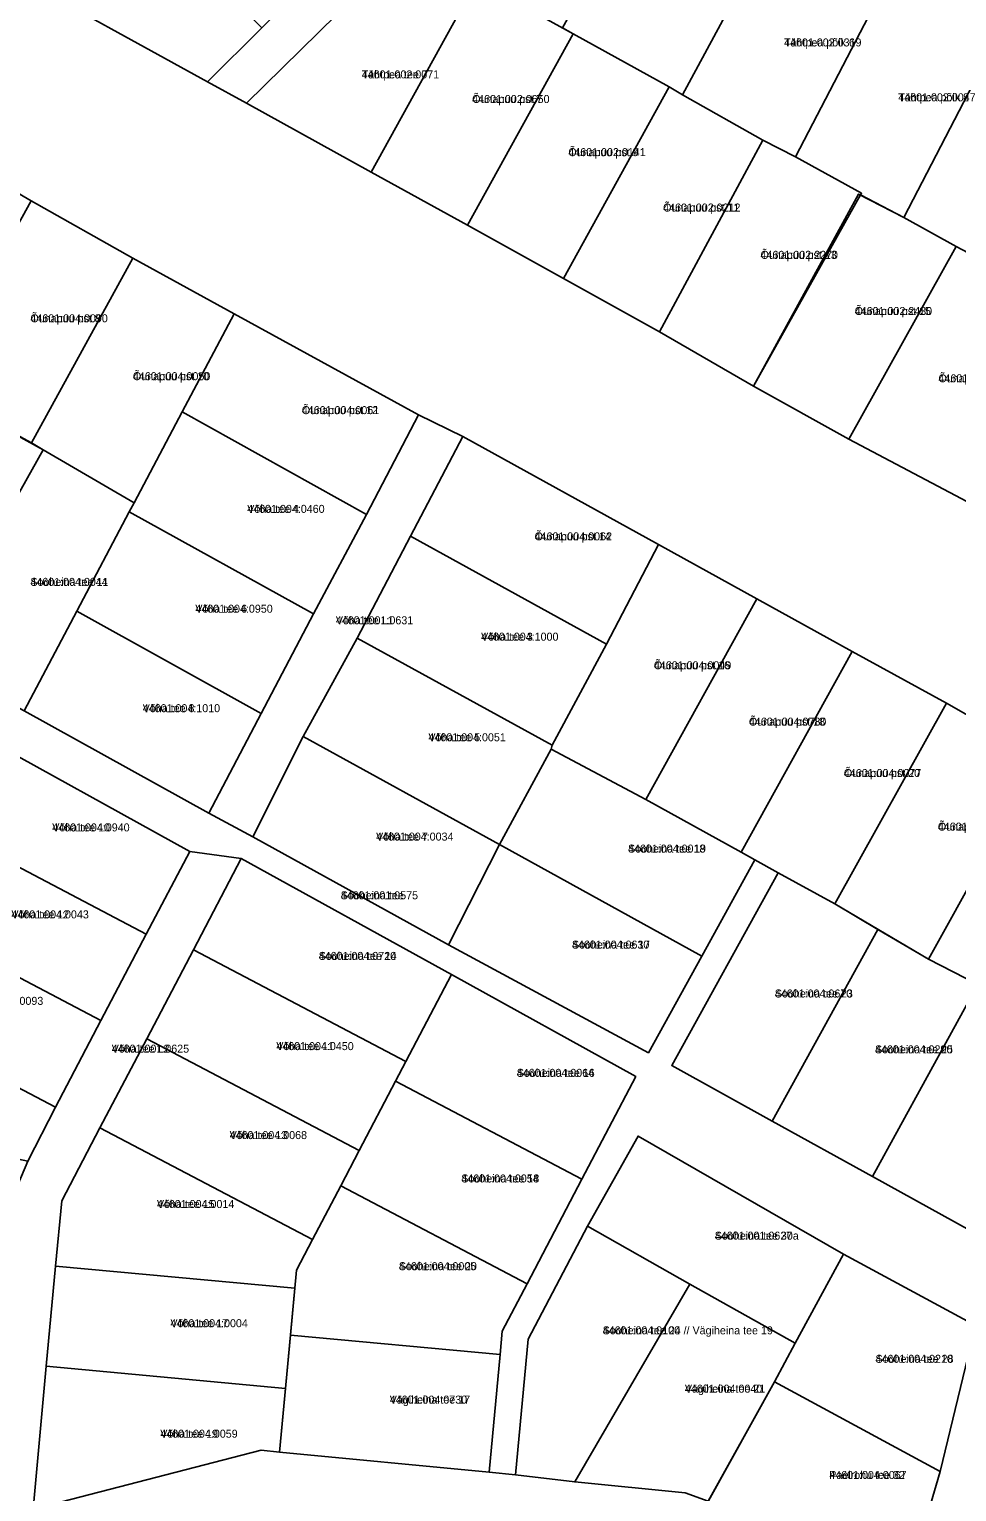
# Model space of a CAD drawing. Extents: x 551843 to 558501, y 6589003 to 6595718.
# Drawn here: x 552201.2 to 552375.1, y 6593331.6 to 6593605.7 of the extents above; entities that cross this region are included whole.
import ezdxf

# ---------------------------------------------------------------- set-up
doc = ezdxf.new("R2010")
doc.units = 0
for name, color, linetype in [('L_AADRESS', 7, 'Continuous'), ('PIIR', 7, 'Continuous'), ('TUNNUS', 7, 'Continuous')]:
    doc.layers.add(name, color=color, linetype=linetype)

msp = doc.modelspace()

# ---------------------------------------------------------------- linework, layer by layer
at = {"layer": 'PIIR'}
for points in [[(552383.34, 6593605.44), (552361.78, 6593614.36), (552339.88, 6593623.2), (552316.12, 6593632.96), (552293.29, 6593642.3), (552272.45, 6593621.81), (552241.95, 6593591.82), (552234.63, 6593595.82), (552244.82, 6593605.97), (552259.44, 6593620.5), (552274.35, 6593634.87), (552288.79, 6593649.43), (552303.37, 6593663.47), (552318.49, 6593678.24), (552333.2, 6593692.7), (552347.91, 6593707.15), (552362.62, 6593721.62), (552378.41, 6593737.13)], [(552196.74, 6593616.79), (552234.63, 6593595.82), (552241.95, 6593591.82), (552265.33, 6593578.91), (552283.35, 6593568.95), (552301.36, 6593558.98), (552319.38, 6593549.02), (552336.96, 6593538.81), (552354.87, 6593528.87), (552378.15, 6593516.55)], [(552390.85, 6593469.35), (552373.17, 6593479.39), (552355.46, 6593489.1), (552337.59, 6593498.96), (552319.2, 6593509.13), (552282.48, 6593529.37), (552274.21, 6593533.45), (552239.65, 6593552.36), (552220.64, 6593562.81), (552201.61, 6593573.54), (552182.84, 6593584.46), (552168.9, 6593592.16), (552132.56, 6593612.13)], [(552200.28, 6593477.95), (552234.92, 6593458.82), (552243.11, 6593454.38), (552279.83, 6593434.14), (552317.27, 6593413.91), (552327.27, 6593432.02), (552337.23, 6593450.05), (552341.61, 6593447.64), (552321.64, 6593411.49), (552340.46, 6593401.09), (552359.28, 6593390.69), (552382.87, 6593377.65)], [(552378.6, 6593362.77), (552353.84, 6593376.18), (552315.33, 6593398.28), (552305.86, 6593381.42), (552294.75, 6593360.25), (552292.38, 6593334.82), (552287.44, 6593335.31), (552289.48, 6593357.36), (552289.88, 6593361.72), (552294.55, 6593370.62), (552304.83, 6593390.23), (552314.92, 6593409.45), (552280.37, 6593428.55), (552240.97, 6593450.32), (552231.31, 6593451.62), (552189.74, 6593474.62)], [(552286.54, 6593173.68), (552301.2, 6593193.36), (552325.99, 6593226.67), (552331.62, 6593234.08), (552351.38, 6593271.55), (552366.78, 6593305.45), (552366.2, 6593315.81), (552371.96, 6593335.44), (552378.6, 6593362.77)], [(552201.95, 6593328.36), (552244.72, 6593339.41), (552248.14, 6593339.08), (552287.44, 6593335.31), (552292.38, 6593334.82), (552303.48, 6593333.49), (552324.18, 6593331.46)]]:
    msp.add_lwpolyline(points, dxfattribs=at)
for points in [[(552244.82, 6593605.97), (552234.63, 6593595.82), (552196.74, 6593616.79), (552211.03, 6593630.85), (552215.73, 6593635.35)], [(552316.12, 6593632.96), (552339.88, 6593623.2), (552338.06, 6593619.88), (552332.47, 6593609.72), (552323.65, 6593593.41), (552321.19, 6593594.87), (552303.17, 6593604.83), (552301.19, 6593605.94)], [(552272.45, 6593621.81), (552285.15, 6593614.8), (552265.33, 6593578.91), (552241.95, 6593591.82)], [(552339.88, 6593623.2), (552361.78, 6593614.36), (552344.87, 6593581.78), (552338.73, 6593584.91), (552323.65, 6593593.41), (552332.47, 6593609.72), (552338.06, 6593619.88)], [(552265.33, 6593578.91), (552285.15, 6593614.8), (552303.17, 6593604.83), (552283.35, 6593568.95)], [(552383.34, 6593605.44), (552365.17, 6593570.42), (552357.05, 6593574.64), (552357.23, 6593574.95), (552344.87, 6593581.78), (552361.78, 6593614.36)], [(552398.63, 6593599.15), (552396.89, 6593594.35), (552392.67, 6593575.27), (552388.43, 6593557.86), (552374.95, 6593565.01), (552365.17, 6593570.42), (552383.34, 6593605.44)], [(552321.19, 6593594.87), (552301.36, 6593558.98), (552283.35, 6593568.95), (552303.17, 6593604.83)], [(552319.38, 6593549.02), (552301.36, 6593558.98), (552321.19, 6593594.87), (552323.65, 6593593.41), (552338.73, 6593584.91)], [(552201.61, 6593573.54), (552182.26, 6593538.65), (552168.62, 6593546.63), (552163.6, 6593549.62), (552182.84, 6593584.46)], [(552319.38, 6593549.02), (552338.73, 6593584.91), (552344.87, 6593581.78), (552357.23, 6593574.95), (552357.05, 6593574.64), (552336.96, 6593538.81)], [(552365.17, 6593570.42), (552374.95, 6593565.01), (552354.87, 6593528.87), (552336.95, 6593538.81), (552356.68, 6593574.8)], [(552220.64, 6593562.81), (552201.67, 6593528.18), (552186.19, 6593536.59), (552182.26, 6593538.65), (552201.61, 6593573.54)], [(552354.87, 6593528.87), (552374.95, 6593565.01), (552388.43, 6593557.86), (552387.5, 6593553.79), (552382.29, 6593532.84), (552378.15, 6593516.55)], [(552203.84, 6593526.91), (552201.67, 6593528.18), (552220.64, 6593562.81), (552239.65, 6593552.36), (552229.91, 6593533.98), (552220.89, 6593516.92)], [(552239.65, 6593552.36), (552274.21, 6593533.45), (552264.42, 6593514.78), (552229.91, 6593533.98)], [(552164.48, 6593497.95), (552186.19, 6593536.59), (552203.84, 6593526.91), (552181.99, 6593487.89)], [(552254.5, 6593496.16), (552219.98, 6593515.24), (552220.89, 6593516.92), (552229.91, 6593533.98), (552264.42, 6593514.78)], [(552244.71, 6593477.49), (552254.5, 6593496.16), (552264.42, 6593514.78), (552274.21, 6593533.45), (552282.48, 6593529.37), (552272.69, 6593510.71), (552262.71, 6593491.61), (552252.56, 6593473.18), (552243.11, 6593454.38), (552234.92, 6593458.82)], [(552282.48, 6593529.37), (552319.2, 6593509.13), (552309.41, 6593490.47), (552272.69, 6593510.71)], [(552220.89, 6593516.92), (552219.98, 6593515.24), (552210.12, 6593496.62), (552200.28, 6593477.95), (552181.99, 6593487.89), (552203.84, 6593526.91)], [(552254.5, 6593496.16), (552244.71, 6593477.49), (552210.12, 6593496.62), (552219.98, 6593515.24)], [(552262.71, 6593491.61), (552272.69, 6593510.71), (552309.41, 6593490.47), (552299.24, 6593471.52)], [(552337.59, 6593498.96), (552316.79, 6593461.33), (552299.03, 6593470.8), (552299.24, 6593471.52), (552309.41, 6593490.47), (552319.2, 6593509.13)], [(552355.46, 6593489.1), (552334.67, 6593451.46), (552316.79, 6593461.33), (552337.59, 6593498.96)], [(552244.71, 6593477.49), (552234.92, 6593458.82), (552200.28, 6593477.95), (552210.12, 6593496.62)], [(552299.24, 6593471.52), (552299.03, 6593470.8), (552289.4, 6593452.93), (552252.56, 6593473.18), (552262.71, 6593491.61)], [(552355.46, 6593489.1), (552373.17, 6593479.39), (552352.22, 6593441.78), (552341.61, 6593447.64), (552337.23, 6593450.05), (552334.67, 6593451.46)], [(552390.85, 6593469.35), (552369.79, 6593431.47), (552352.22, 6593441.78), (552373.17, 6593479.39)], [(552231.31, 6593451.62), (552223.17, 6593436.13), (552181.12, 6593458.23), (552184.09, 6593463.87), (552188.39, 6593472.05), (552189.74, 6593474.62)], [(552289.4, 6593452.93), (552279.83, 6593434.14), (552243.11, 6593454.38), (552252.56, 6593473.18)], [(552337.23, 6593450.05), (552327.27, 6593432.02), (552289.4, 6593452.93), (552299.03, 6593470.8), (552316.79, 6593461.33), (552334.67, 6593451.46)], [(552390.85, 6593469.35), (552405.48, 6593461.46), (552393.51, 6593418.63), (552379.05, 6593426.69), (552369.79, 6593431.47)], [(552214.65, 6593419.93), (552172.61, 6593442.03), (552181.12, 6593458.23), (552223.17, 6593436.13)], [(552231.31, 6593451.62), (552240.97, 6593450.32), (552231.99, 6593433.2), (552223.24, 6593416.52), (552214.49, 6593399.84), (552207.31, 6593386.18), (552206.17, 6593373.94), (552204.43, 6593355.18), (552201.95, 6593328.36), (552192.41, 6593323.77), (552195.94, 6593365.07), (552199.1, 6593389.17), (552200.97, 6593393.62), (552206.12, 6593403.72), (552214.65, 6593419.93), (552223.17, 6593436.13)], [(552279.83, 6593434.14), (552289.4, 6593452.93), (552327.27, 6593432.02), (552317.27, 6593413.91)], [(552240.97, 6593450.32), (552280.37, 6593428.55), (552271.84, 6593412.29), (552231.99, 6593433.2)], [(552341.61, 6593447.64), (552352.22, 6593441.78), (552360.31, 6593437.03), (552340.46, 6593401.09), (552321.64, 6593411.49)], [(552214.65, 6593419.93), (552206.12, 6593403.72), (552164.07, 6593425.82), (552172.61, 6593442.03)], [(552340.46, 6593401.09), (552360.31, 6593437.03), (552369.79, 6593431.47), (552379.05, 6593426.69), (552359.28, 6593390.69)], [(552271.84, 6593412.29), (552269.88, 6593408.57), (552263.09, 6593395.61), (552223.24, 6593416.52), (552231.99, 6593433.2)], [(552304.83, 6593390.23), (552269.88, 6593408.57), (552271.84, 6593412.29), (552280.37, 6593428.55), (552314.92, 6593409.45)], [(552164.07, 6593425.82), (552206.12, 6593403.72), (552200.97, 6593393.62), (552152.74, 6593403.96)], [(552382.87, 6593377.65), (552359.28, 6593390.69), (552379.05, 6593426.69), (552393.51, 6593418.63)], [(552214.49, 6593399.84), (552223.24, 6593416.52), (552263.09, 6593395.61), (552259.6, 6593388.97), (552254.34, 6593378.93)], [(552294.55, 6593370.62), (552259.6, 6593388.97), (552263.09, 6593395.61), (552269.88, 6593408.57), (552304.83, 6593390.23)], [(552254.34, 6593378.93), (552251.3, 6593373.15), (552250.98, 6593369.78), (552206.17, 6593373.94), (552207.31, 6593386.18), (552214.49, 6593399.84)], [(552305.86, 6593381.42), (552315.33, 6593398.28), (552353.84, 6593376.18), (552344.77, 6593359.49), (552325.05, 6593370.55)], [(552251.3, 6593373.15), (552254.34, 6593378.93), (552259.6, 6593388.97), (552294.55, 6593370.62), (552289.88, 6593361.72), (552289.48, 6593357.36), (552250.17, 6593361.01)], [(552325.05, 6593370.55), (552303.48, 6593333.49), (552292.38, 6593334.82), (552294.75, 6593360.25), (552305.86, 6593381.42)], [(552371.96, 6593335.44), (552340.89, 6593352.26), (552344.77, 6593359.49), (552353.84, 6593376.18), (552378.6, 6593362.77)], [(552204.43, 6593355.18), (552206.17, 6593373.94), (552250.98, 6593369.78), (552249.24, 6593351.01)], [(552344.77, 6593359.49), (552340.89, 6593352.26), (552328.5, 6593329.85), (552324.18, 6593331.46), (552303.48, 6593333.49), (552325.05, 6593370.55)], [(552287.44, 6593335.31), (552248.14, 6593339.08), (552250.17, 6593361.01), (552289.48, 6593357.36)], [(552244.72, 6593339.41), (552201.95, 6593328.36), (552204.43, 6593355.18), (552249.24, 6593351.01), (552248.14, 6593339.08)], [(552328.5, 6593329.85), (552328.54, 6593329.92), (552340.89, 6593352.26), (552371.96, 6593335.44), (552366.2, 6593315.81)]]:
    msp.add_lwpolyline(points, close=True, dxfattribs=at)

# ---------------------------------------------------------------- texts
at = {"layer": 'L_AADRESS'}
for s, p in [('Tähtpea põik 6', (552342.71, 6593602.47)), ('Tähtpea tee 7', (552263.55, 6593596.48)), ('Õunapuu pst 7', (552284.25, 6593591.87)), ('Tähtpea põik 8', (552364.11, 6593592.19)), ('Õunapuu pst 9', (552302.27, 6593581.91)), ('Õunapuu pst 11', (552320.04, 6593571.53)), ('Õunapuu pst 13', (552338.3, 6593562.67)), ('Õunapuu pst 15', (552355.95, 6593552.14)), ('Õunapuu pst 8', (552201.45, 6593550.78)), ('Õunapuu pst 10', (552220.66, 6593539.93)), ('Õunapuu pst 17', (552371.65, 6593539.53)), ('Õunapuu pst 12', (552252.32, 6593533.57)), ('Võha tee 4', (552242.09, 6593515.07)), ('Õunapuu pst 14', (552295.95, 6593509.92)), ('Sooheina tee 11', (552201.44, 6593501.39)), ('Võha tee 6', (552232.36, 6593496.36)), ('Võha tee L1', (552258.7, 6593494.19)), ('Võha tee 3', (552285.92, 6593491.12)), ('Õunapuu pst 16', (552318.31, 6593485.76)), ('Võha tee 8', (552222.5, 6593477.72)), ('Õunapuu pst 18', (552336.12, 6593475.2)), ('Võha tee 5', (552276.05, 6593472.27)), ('Õunapuu pst 20', (552353.92, 6593465.57)), ('Võha tee 10', (552205.54, 6593455.38)), ('Õunapuu pst 22', (552371.54, 6593455.53)), ('Võha tee 7', (552266.24, 6593453.66)), ('Sooheina tee 19', (552313.46, 6593451.41)), ('Sooheina tee', (552259.6, 6593442.66)), ('Võha tee 12', (552197.89, 6593439.08)), ('Sooheina tee 14', (552255.49, 6593431.3)), ('Sooheina tee 17', (552302.95, 6593433.42)), ('Sooheina tee 23', (552340.98, 6593424.26)), ('Võha tee 11', (552247.54, 6593414.4)), ('Võha tee L2', (552216.69, 6593413.92)), ('Sooheina tee 25', (552359.75, 6593413.79)), ('Sooheina tee 16', (552292.6, 6593409.39)), ('Võha tee 13', (552238.79, 6593397.73)), ('Sooheina tee 18', (552282.21, 6593389.6)), ('Võha tee 15', (552225.16, 6593384.81)), ('Sooheina tee 30a', (552329.73, 6593378.88)), ('Sooheina tee 20', (552270.51, 6593373.16)), ('Võha tee 17', (552227.7, 6593362.48)), ('Sooheina tee 24 // Vägiheina tee 19', (552308.71, 6593361.14)), ('Sooheina tee 28', (552359.85, 6593355.81)), ('Vägiheina tee 21', (552324.12, 6593350.21)), ('Vägiheina tee 17', (552268.8, 6593348.16)), ('Võha tee 19', (552225.79, 6593341.77)), ('Paelrohu tee 32', (552351.18, 6593334.04))]:
    msp.add_text(s, height=1.5, dxfattribs=at).set_placement(p)
at = {"layer": 'TUNNUS'}
for s, p in [('44601:002:0319', (552342.71, 6593602.47)), ('44601:002:0071', (552263.55, 6593596.48)), ('44601:002:0650', (552284.25, 6593591.87)), ('44601:002:0047', (552364.11, 6593592.19)), ('44601:002:0141', (552302.27, 6593581.91)), ('44601:002:0212', (552320.04, 6593571.53)), ('44601:002:2270', (552338.3, 6593562.67)), ('44601:002:2430', (552355.95, 6593552.14)), ('44601:004:0090', (552201.45, 6593550.78)), ('44601:004:0050', (552220.66, 6593539.93)), ('44601:002:2290', (552371.65, 6593539.53)), ('44601:004:0061', (552252.32, 6593533.57)), ('44601:004:0460', (552242.09, 6593515.07)), ('44601:004:0062', (552295.95, 6593509.92)), ('44601:004:0044', (552201.44, 6593501.39)), ('44601:004:0950', (552232.36, 6593496.36)), ('44601:001:0631', (552258.7, 6593494.19)), ('44601:004:1000', (552285.92, 6593491.12)), ('44601:004:0049', (552318.31, 6593485.76)), ('44601:004:1010', (552222.5, 6593477.72)), ('44601:004:0780', (552336.12, 6593475.2)), ('44601:004:0051', (552276.05, 6593472.27)), ('44601:004:0077', (552353.92, 6593465.57)), ('44601:004:0015', (552371.54, 6593455.53)), ('44601:004:0940', (552205.54, 6593455.38)), ('44601:004:0034', (552266.24, 6593453.66)), ('44601:004:0018', (552313.46, 6593451.41)), ('44601:001:0575', (552259.6, 6593442.66)), ('44601:004:0043', (552197.89, 6593439.08)), ('44601:004:0720', (552255.49, 6593431.3)), ('44601:004:0630', (552302.95, 6593433.42)), ('44601:004:0093', (552189.36, 6593422.88)), ('44601:004:0670', (552340.98, 6593424.26)), ('44601:004:0450', (552247.54, 6593414.4)), ('44601:001:0625', (552216.69, 6593413.92)), ('44601:004:0290', (552359.75, 6593413.79)), ('44601:004:0064', (552292.6, 6593409.39)), ('44601:004:0068', (552238.79, 6593397.73)), ('44601:004:0054', (552282.21, 6593389.6)), ('44601:004:0014', (552225.16, 6593384.81)), ('44601:001:0627', (552329.73, 6593378.88)), ('44601:004:0005', (552270.51, 6593373.16)), ('44601:004:0004', (552227.7, 6593362.48)), ('44601:004:0100', (552308.71, 6593361.14)), ('44601:004:0210', (552359.85, 6593355.81)), ('44601:004:0040', (552324.12, 6593350.21)), ('44601:004:0730', (552268.8, 6593348.16)), ('44601:004:0059', (552225.79, 6593341.77)), ('44601:004:0067', (552351.18, 6593334.04))]:
    msp.add_text(s, height=1.5, dxfattribs=at).set_placement(p)

doc.saveas('drawing.dxf')
